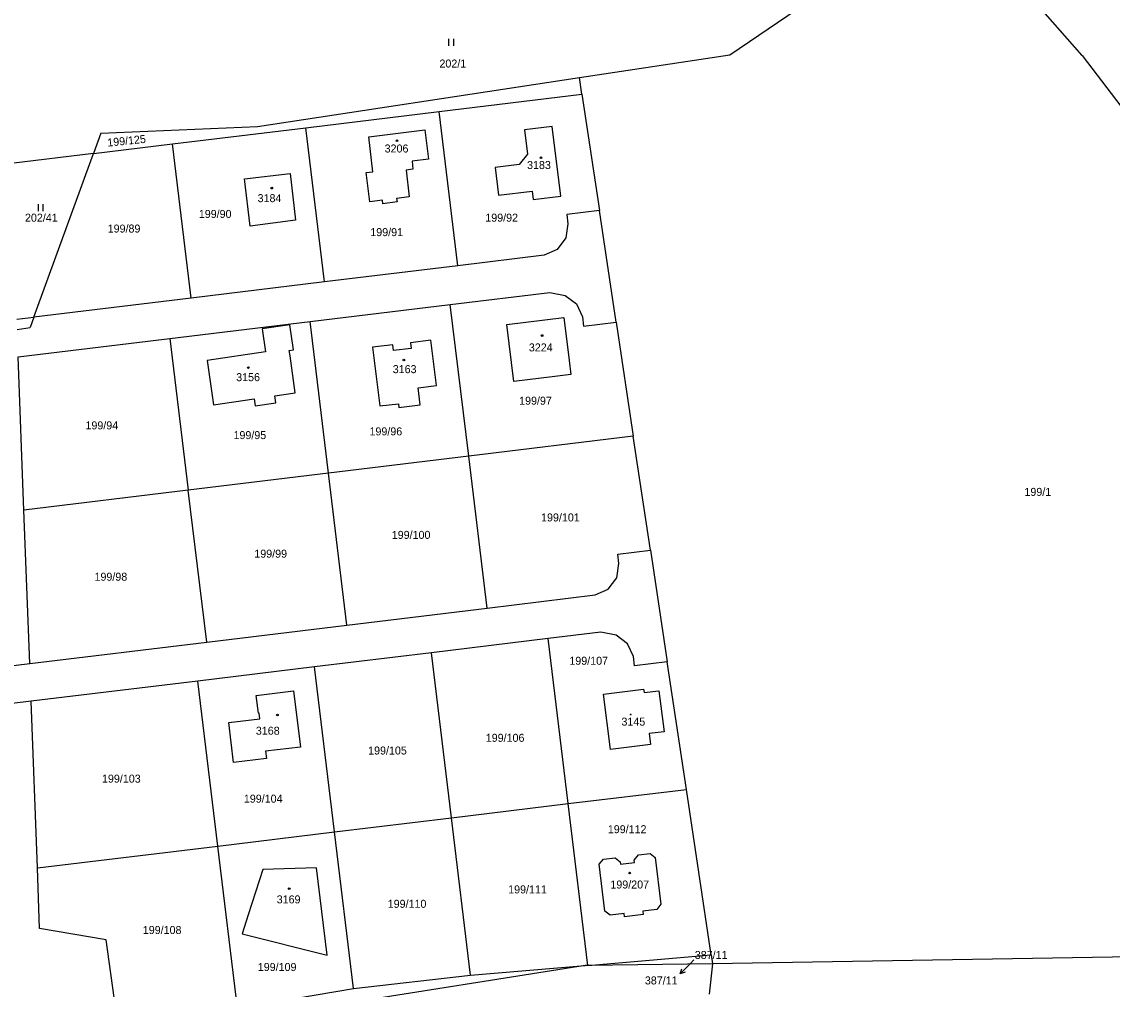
# Model space of a CAD drawing. Extents: x -735249 to -729401, y -1124843 to -1121828.
# Drawn here: x -732832.6 to -732600.9, y -1123749.1 to -1123543.4 of the extents above; entities that cross this region are included whole.
import ezdxf

# ---------------------------------------------------------------- set-up
doc = ezdxf.new("R2010")
doc.units = 0
for name, color, linetype in [('Vrstva 1', 7, 'Continuous'), ('Vrstva 16', 7, 'Continuous'), ('Vrstva 18', 7, 'Continuous'), ('Vrstva 19', 7, 'Continuous'), ('Vrstva 25', 7, 'Continuous')]:
    doc.layers.add(name, color=color, linetype=linetype)

msp = doc.modelspace()

# ---------------------------------------------------------------- linework, layer by layer
at = {"layer": 'Vrstva 1'}
for points in [[(-732607.31, -1123550.57), (-732635.91, -1123517.96)], [(-732682.19, -1123550.44), (-732667.85, -1123540.71)], [(-732714.12, -1123555.24), (-732682.19, -1123550.44)], [(-732607.31, -1123550.57), (-732585.65, -1123578.98)], [(-732782.48, -1123565.68), (-732714.12, -1123555.24)], [(-732713.58, -1123558.81), (-732714.12, -1123555.24)], [(-732743.89, -1123562.49), (-732713.58, -1123558.81)], [(-732713.58, -1123558.81), (-732709.87, -1123583.54)], [(-732772.25, -1123565.93), (-732743.89, -1123562.49)], [(-732739.92, -1123595.24), (-732743.89, -1123562.49)], [(-732815.8, -1123567.05), (-732817.38, -1123571.4)], [(-732815.8, -1123567.05), (-732782.48, -1123565.68)], [(-732800.6, -1123569.36), (-732772.25, -1123565.93)], [(-732768.28, -1123598.69), (-732772.25, -1123565.93)], [(-732758.87, -1123567.84), (-732746.94, -1123566.37)], [(-732746.94, -1123566.37), (-732746.19, -1123572.58)], [(-732719.9, -1123565.64), (-732725.78, -1123566.37)], [(-732725.78, -1123566.37), (-732725.13, -1123571.53)], [(-732718.06, -1123580.45), (-732719.9, -1123565.64)], [(-732817.38, -1123571.4), (-732800.6, -1123569.36)], [(-732796.63, -1123602.13), (-732800.6, -1123569.36)], [(-732757.98, -1123575.3), (-732758.87, -1123567.84)], [(-732817.38, -1123571.4), (-732834.87, -1123573.52)], [(-732830, -1123606.18), (-732817.38, -1123571.4)], [(-732725.13, -1123571.53), (-732726.9, -1123573.76)], [(-732746.19, -1123572.58), (-732749.67, -1123573.01)], [(-732749.67, -1123573.01), (-732749.48, -1123574.75)], [(-732726.9, -1123573.76), (-732732.04, -1123574.4)], [(-732732.04, -1123574.4), (-732731.31, -1123580.26)], [(-732785.25, -1123576.81), (-732775.6, -1123575.64)], [(-732784.08, -1123586.81), (-732785.25, -1123576.81)], [(-732775.6, -1123575.64), (-732774.45, -1123585.58)], [(-732759.44, -1123575.45), (-732757.98, -1123575.3)], [(-732758.66, -1123581.66), (-732759.44, -1123575.45)], [(-732749.48, -1123574.75), (-732750.95, -1123574.94)], [(-732750.95, -1123574.94), (-732750.26, -1123580.64)], [(-732755.97, -1123581.34), (-732758.66, -1123581.66)], [(-732755.86, -1123582.06), (-732755.97, -1123581.34)], [(-732750.26, -1123580.64), (-732752.97, -1123580.98)], [(-732752.97, -1123580.98), (-732752.87, -1123581.7)], [(-732731.31, -1123580.26), (-732724.18, -1123579.37)], [(-732724.18, -1123579.37), (-732723.95, -1123581.17)], [(-732723.95, -1123581.17), (-732718.06, -1123580.45)], [(-732752.87, -1123581.7), (-732755.86, -1123582.06)], [(-732709.87, -1123583.54), (-732716.83, -1123584.38)], [(-732706.3, -1123607.28), (-732709.87, -1123583.54)], [(-732774.45, -1123585.58), (-732784.08, -1123586.81)], [(-732716.83, -1123584.38), (-732716.59, -1123586.37)], [(-732716.59, -1123586.37), (-732717.03, -1123589.34)], [(-732717.03, -1123589.34), (-732718.83, -1123591.77)], [(-732721.59, -1123593.02), (-732739.92, -1123595.24)], [(-732718.83, -1123591.77), (-732721.59, -1123593.02)], [(-732739.92, -1123595.24), (-732768.28, -1123598.69)], [(-732768.28, -1123598.69), (-732796.63, -1123602.13)], [(-732796.63, -1123602.13), (-732830, -1123606.18)], [(-732741.57, -1123603.5), (-732720.4, -1123600.94)], [(-732720.4, -1123600.94), (-732717.17, -1123601.57)], [(-732717.17, -1123601.57), (-732714.75, -1123603.38)], [(-732771.35, -1123607.12), (-732741.57, -1123603.5)], [(-732737.65, -1123635.77), (-732741.57, -1123603.5)], [(-732714.75, -1123603.38), (-732713.49, -1123606.13)], [(-732833.63, -1123606.6), (-732830, -1123606.18)], [(-732830, -1123606.18), (-732830.81, -1123608.4)], [(-732729.53, -1123607.75), (-732717.42, -1123606.28)], [(-732717.42, -1123606.28), (-732716.31, -1123615.4)], [(-732713.49, -1123606.13), (-732713.25, -1123608.12)], [(-732833.55, -1123608.79), (-732830.81, -1123608.4)], [(-732801.13, -1123610.73), (-732771.35, -1123607.12)], [(-732775.65, -1123607.8), (-732781.53, -1123608.68)], [(-732781.53, -1123608.68), (-732780.79, -1123613.57)], [(-732774.86, -1123613.12), (-732775.65, -1123607.8)], [(-732767.44, -1123639.38), (-732771.35, -1123607.12)], [(-732728.07, -1123619.86), (-732729.53, -1123607.75)], [(-732713.25, -1123608.12), (-732706.3, -1123607.28)], [(-732706.3, -1123607.28), (-732702.67, -1123631.52)], [(-732833.34, -1123614.64), (-732801.13, -1123610.73)], [(-732801.13, -1123610.73), (-732797.21, -1123642.99)], [(-732745.68, -1123611.1), (-732750.01, -1123611.61)], [(-732750.01, -1123611.61), (-732749.88, -1123612.83)], [(-732744.48, -1123620.73), (-732745.68, -1123611.1)], [(-732780.79, -1123613.57), (-732793.19, -1123615.41)], [(-732775.77, -1123613.25), (-732774.86, -1123613.12)], [(-732775.6, -1123614.43), (-732775.77, -1123613.25)], [(-732753.77, -1123612.07), (-732758.08, -1123612.59)], [(-732758.08, -1123612.59), (-732756.55, -1123625.07)], [(-732753.63, -1123613.3), (-732753.77, -1123612.07)], [(-732749.88, -1123612.83), (-732753.63, -1123613.3)], [(-732832.12, -1123647.23), (-732833.34, -1123614.64)], [(-732793.19, -1123615.41), (-732791.84, -1123624.79)], [(-732774.48, -1123622.26), (-732775.6, -1123614.43)], [(-732716.31, -1123615.4), (-732715.93, -1123618.37)], [(-732715.93, -1123618.37), (-732719.34, -1123618.81)], [(-732748.35, -1123621.21), (-732744.48, -1123620.73)], [(-732719.34, -1123618.81), (-732728.07, -1123619.86)], [(-732778.83, -1123622.9), (-732774.48, -1123622.26)], [(-732778.62, -1123624.38), (-732778.83, -1123622.9)], [(-732747.93, -1123624.84), (-732748.35, -1123621.21)], [(-732791.84, -1123624.79), (-732783.19, -1123623.55)], [(-732783.19, -1123623.55), (-732783.02, -1123625.03)], [(-732783.02, -1123625.03), (-732778.62, -1123624.38)], [(-732756.55, -1123625.07), (-732752.57, -1123624.6)], [(-732752.57, -1123624.6), (-732752.48, -1123625.39)], [(-732752.48, -1123625.39), (-732747.93, -1123624.84)], [(-732702.67, -1123631.52), (-732737.65, -1123635.77)], [(-732699.03, -1123655.75), (-732702.67, -1123631.52)], [(-732737.65, -1123635.77), (-732767.44, -1123639.38)], [(-732733.74, -1123668.03), (-732737.65, -1123635.77)], [(-732767.44, -1123639.38), (-732797.21, -1123642.99)], [(-732763.52, -1123671.64), (-732767.44, -1123639.38)], [(-732797.21, -1123642.99), (-732832.12, -1123647.23)], [(-732793.3, -1123675.25), (-732797.21, -1123642.99)], [(-732830.9, -1123679.81), (-732832.12, -1123647.23)], [(-732705.98, -1123656.6), (-732699.03, -1123655.75)], [(-732705.74, -1123658.59), (-732705.98, -1123656.6)], [(-732699.03, -1123655.75), (-732695.47, -1123679.49)], [(-732706.18, -1123661.57), (-732705.74, -1123658.59)], [(-732707.99, -1123663.99), (-732706.18, -1123661.57)], [(-732710.75, -1123665.24), (-732707.99, -1123663.99)], [(-732733.74, -1123668.03), (-732710.75, -1123665.24)], [(-732763.52, -1123671.64), (-732733.74, -1123668.03)], [(-732793.3, -1123675.25), (-732763.52, -1123671.64)], [(-732709.57, -1123673.15), (-732720.76, -1123674.51)], [(-732706.33, -1123673.79), (-732709.57, -1123673.15)], [(-732703.92, -1123675.6), (-732706.33, -1123673.79)], [(-732830.9, -1123679.81), (-732793.3, -1123675.25)], [(-732720.76, -1123674.51), (-732745.58, -1123677.52)], [(-732716.51, -1123709.61), (-732720.76, -1123674.51)], [(-732702.66, -1123678.35), (-732703.92, -1123675.6)], [(-732745.58, -1123677.52), (-732770.39, -1123680.53)], [(-732741.33, -1123712.62), (-732745.58, -1123677.52)], [(-732702.42, -1123680.34), (-732702.66, -1123678.35)], [(-732847.91, -1123681.88), (-732830.9, -1123679.81)], [(-732770.39, -1123680.53), (-732795.21, -1123683.54)], [(-732766.14, -1123715.62), (-732770.39, -1123680.53)], [(-732695.47, -1123679.49), (-732702.42, -1123680.34)], [(-732691.4, -1123706.57), (-732695.47, -1123679.49)], [(-732795.21, -1123683.54), (-732830.6, -1123687.83)], [(-732790.96, -1123718.63), (-732795.21, -1123683.54)], [(-732782.77, -1123686.64), (-732774.88, -1123685.65)], [(-732774.88, -1123685.65), (-732773.4, -1123697.58)], [(-732709.04, -1123686.34), (-732700.49, -1123685.28)], [(-732700.49, -1123685.28), (-732700.38, -1123685.99)], [(-732700.38, -1123685.99), (-732697.22, -1123685.6)], [(-732697.22, -1123685.6), (-732696.11, -1123694.31)], [(-732830.6, -1123687.83), (-732846.84, -1123689.8)], [(-732829.28, -1123723.27), (-732830.6, -1123687.83)], [(-732782.3, -1123690.4), (-732782.77, -1123686.64)], [(-732707.51, -1123698.07), (-732709.04, -1123686.34)], [(-732782.15, -1123690.38), (-732782.3, -1123690.4)], [(-732782, -1123691.56), (-732782.15, -1123690.38)], [(-732788.63, -1123692.37), (-732782, -1123691.56)], [(-732787.62, -1123700.84), (-732788.63, -1123692.37)], [(-732696.11, -1123694.31), (-732699.28, -1123694.73)], [(-732699.28, -1123694.73), (-732699.04, -1123697.01)], [(-732699.04, -1123697.01), (-732707.51, -1123698.07)], [(-732773.4, -1123697.58), (-732780.81, -1123698.48)], [(-732780.81, -1123698.48), (-732780.63, -1123699.98)], [(-732780.63, -1123699.98), (-732787.62, -1123700.84)], [(-732716.51, -1123709.61), (-732691.4, -1123706.57)], [(-732686.12, -1123741.75), (-732691.4, -1123706.57)], [(-732741.33, -1123712.62), (-732716.51, -1123709.61)], [(-732712.35, -1123743.98), (-732716.51, -1123709.61)], [(-732766.14, -1123715.62), (-732741.33, -1123712.62)], [(-732737.28, -1123746.09), (-732741.33, -1123712.62)], [(-732790.96, -1123718.63), (-732766.14, -1123715.62)], [(-732762.11, -1123748.87), (-732766.14, -1123715.62)], [(-732829.28, -1123723.27), (-732790.96, -1123718.63)], [(-732786.79, -1123753.06), (-732790.96, -1123718.63)], [(-732702.47, -1123721.6), (-732701.6, -1123720.48)], [(-732701.6, -1123720.48), (-732699.1, -1123720.19)], [(-732699.1, -1123720.19), (-732698.01, -1123721.06)], [(-732709.91, -1123722.5), (-732709.04, -1123721.4)], [(-732708.71, -1123732.45), (-732709.91, -1123722.5)], [(-732709.04, -1123721.4), (-732706.55, -1123721.1)], [(-732706.55, -1123721.1), (-732705.46, -1123721.96)], [(-732705.46, -1123721.96), (-732705.39, -1123722.47)], [(-732705.39, -1123722.47), (-732702.4, -1123722.09)], [(-732702.4, -1123722.09), (-732702.47, -1123721.6)], [(-732698.01, -1123721.06), (-732696.8, -1123730.99)], [(-732828.8, -1123736.13), (-732829.28, -1123723.27)], [(-732781.35, -1123723.62), (-732784.48, -1123733.26)], [(-732770, -1123723.22), (-732781.35, -1123723.62)], [(-732767.68, -1123741.82), (-732770, -1123723.22)], [(-732697.66, -1123732.1), (-732700.65, -1123732.46)], [(-732696.8, -1123730.99), (-732697.66, -1123732.1)], [(-732784.48, -1123733.26), (-732785.78, -1123737.29)], [(-732707.61, -1123733.31), (-732708.71, -1123732.45)], [(-732704.62, -1123732.95), (-732707.61, -1123733.31)], [(-732704.54, -1123733.64), (-732704.62, -1123732.95)], [(-732700.58, -1123733.15), (-732704.54, -1123733.64)], [(-732700.65, -1123732.46), (-732700.58, -1123733.15)], [(-732814.66, -1123738.59), (-732828.8, -1123736.13)], [(-732811.88, -1123758.45), (-732814.66, -1123738.59)], [(-732785.78, -1123737.29), (-732767.68, -1123741.82)], [(-732712.35, -1123743.98), (-732686.12, -1123741.75)], [(-732685.84, -1123743.64), (-732712.35, -1123743.98)], [(-732685.84, -1123743.64), (-732686.53, -1123750.08)], [(-732686.12, -1123741.75), (-732685.84, -1123743.64)], [(-732592.36, -1123742.09), (-732685.84, -1123743.64)], [(-732712.93, -1123744.02), (-732818.4, -1123760.76)], [(-732737.28, -1123746.09), (-732712.93, -1123744.02)], [(-732712.35, -1123743.98), (-732712.93, -1123744.02)], [(-732762.11, -1123748.87), (-732737.28, -1123746.09)], [(-732786.79, -1123753.06), (-732762.11, -1123748.87)]]:
    msp.add_lwpolyline(points, dxfattribs=at)
at = {"layer": 'Vrstva 16'}
msp.add_lwpolyline([(-732689.81, -1123742.82), (-732690.61, -1123743.65)], dxfattribs=at)
at = {"layer": 'Vrstva 25'}
for points in [[(-732741.867, -1123548.495), (-732741.867, -1123546.995)], [(-732740.833, -1123548.495), (-732740.833, -1123546.995)], [(-732829.047, -1123583.655), (-732829.047, -1123582.155)], [(-732828.013, -1123583.655), (-732828.013, -1123582.155)], [(-732690.61, -1123743.65), (-732692.697, -1123745.804)], [(-732691.642, -1123745.434), (-732692.697, -1123745.804), (-732692.36, -1123744.738)]]:
    msp.add_lwpolyline(points, dxfattribs=at)
for centre, radius in [((-732752.89, -1123568.69), 0.175), ((-732722.3, -1123572.31), 0.175), ((-732779.47, -1123578.75), 0.175), ((-732722.04, -1123610.1), 0.175), ((-732751.42, -1123615.3), 0.175), ((-732784.45, -1123616.91), 0.175), ((-732778.28, -1123690.78), 0.175), ((-732703.23, -1123690.65), 0.0875), ((-732703.46, -1123724.36), 0.175), ((-732775.77, -1123727.67), 0.175)]:
    msp.add_circle(centre, radius, dxfattribs=at)

# ---------------------------------------------------------------- texts
at = {"layer": 'Vrstva 16'}
msp.add_text('387/11', height=1.7, dxfattribs=at).set_placement((-732700.217, -1123748.04))
at = {"layer": 'Vrstva 18'}
for s, p in [('202/1', (-732743.86, -1123553.12)), ('199/90', (-732794.98, -1123585.09)), ('202/41', (-732831.91, -1123585.89)), ('199/92', (-732734.12, -1123585.89)), ('199/89', (-732814.34, -1123588.2)), ('199/91', (-732758.55, -1123588.96)), ('199/97', (-732726.93, -1123624.8)), ('199/94', (-732819.06, -1123630.04)), ('199/96', (-732758.72, -1123631.32)), ('199/95', (-732787.61, -1123632.11)), ('199/1', (-732619.58, -1123644.18)), ('199/101', (-732722.27, -1123649.61)), ('199/100', (-732753.99, -1123653.32)), ('199/99', (-732783.19, -1123657.32)), ('199/98', (-732817.14, -1123662.22)), ('199/107', (-732716.26, -1123680.08)), ('199/106', (-732734.02, -1123696.46)), ('199/105', (-732759.01, -1123699.16)), ('199/103', (-732815.55, -1123705.14)), ('199/104', (-732785.41, -1123709.4)), ('199/112', (-732708.088, -1123715.89)), ('199/111', (-732729.26, -1123728.69)), ('199/110', (-732754.85, -1123731.75)), ('199/108', (-732806.88, -1123737.32)), ('387/11', (-732689.61, -1123742.62)), ('199/109', (-732782.45, -1123745.18))]:
    msp.add_text(s, height=1.7, dxfattribs=at).set_placement(p)
msp.add_text('199/125', height=1.7, rotation=5.80005, dxfattribs=at).set_placement((-732814.332, -1123569.941))
at = {"layer": 'Vrstva 19'}
for s, p in [('3206', (-732755.503, -1123571.18)), ('3183', (-732725.243, -1123574.69)), ('3184', (-732782.493, -1123581.74)), ('3224', (-732724.863, -1123613.47)), ('3163', (-732753.783, -1123618.09)), ('3156', (-732787.043, -1123619.79)), ('3145', (-732705.193, -1123693.02)), ('3168', (-732782.863, -1123694.95)), ('199/207', (-732707.548, -1123727.65)), ('3169', (-732778.433, -1123730.81))]:
    msp.add_text(s, height=1.7, dxfattribs=at).set_placement(p)

doc.saveas('drawing.dxf')
